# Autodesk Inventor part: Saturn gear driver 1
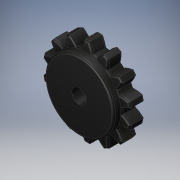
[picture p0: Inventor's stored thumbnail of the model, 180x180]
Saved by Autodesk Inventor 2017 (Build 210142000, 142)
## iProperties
Created: 2016-06
Part Number: Saturn gear driver 1
Material: Generic
Document SubType Name: Modeling
Designer: Stan
Density: 1 g/cm^3
Appearance: Glossy - Black
Author: Stan
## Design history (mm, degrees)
sketch "Sketch1" dims "d10" = 6.35
  geometry: A1 r 11.332 centre (-15.835, 1.665) between (-10.35, 11.581) and (-14.449, 12.912); A2 r 11.332 centre (-15.835, 1.665) between (-10.35, 11.581) and (-14.449, 12.912); A3 r 11.332 centre (1.9, 15.808) between (-9.373, 16.96) and (-8.988, 12.667); A4 r 11.332 centre (1.9, 15.808) between (-9.373, 16.96) and (-8.988, 12.667); A5 r 11.332 centre (-14.989, -5.37) between (-14.35, 5.944) and (-18.62, 5.364); A6 r 11.332 centre (-14.989, -5.37) between (-14.35, 5.944) and (-18.62, 5.364); A7 r 11.332 centre (-5.147, 15.067) between (-15.803, 11.213) and (-13.594, 7.513); A8 r 11.332 centre (-5.147, 15.067) between (-15.803, 11.213) and (-13.594, 7.513); A9 r 11.332 centre (-11.175, -11.342) between (-15.507, -0.871) and (-19.104, -3.246); A10 r 11.332 centre (-11.175, -11.342) between (-15.507, -0.871) and (-19.104, -3.246); A11 r 11.332 centre (-11.175, 11.342) between (-19.104, 3.246) and (-15.507, 0.871); A12 r 11.332 centre (-11.175, 11.342) between (-19.104, 3.246) and (-15.507, 0.871); A13 r 11.332 centre (-5.147, -15.067) between (-13.594, -7.513) and (-15.803, -11.213); A14 r 11.332 centre (-5.147, -15.067) between (-13.594, -7.513) and (-15.803, -11.213); A15 r 11.332 centre (-14.989, 5.37) between (-18.62, -5.364) and (-14.35, -5.944); A16 r 11.332 centre (-14.989, 5.37) between (-18.62, -5.364) and (-14.35, -5.944); A17 r 11.332 centre (1.9, -15.808) between (-8.988, -12.667) and (-9.373, -16.96); A18 r 11.332 centre (1.9, -15.808) between (-8.988, -12.667) and (-9.373, -16.96); A19 r 11.332 centre (-15.835, -1.665) between (-14.449, -12.912) and (-10.35, -11.581); A20 r 11.332 centre (-15.835, -1.665) between (-14.449, -12.912) and (-10.35, -11.581); A21 r 11.332 centre (8.571, -13.418) between (-2.602, -15.312) and (-1.086, -19.347); A22 r 11.332 centre (8.571, -13.418) between (-2.602, -15.312) and (-1.086, -19.347); A23 r 11.332 centre (-13.544, -8.371) between (-7.415, -17.902) and (-4.3, -14.925); A24 r 11.332 centre (-13.544, -8.371) between (-7.415, -17.902) and (-4.3, -14.925); A25 r 11.332 centre (13.544, -8.371) between (4.3, -14.925) and (7.415, -17.902); A26 r 11.332 centre (13.544, -8.371) between (4.3, -14.925) and (7.415, -17.902); A27 r 11.332 centre (-8.571, -13.418) between (1.086, -19.347) and (2.602, -15.312); A28 r 11.332 centre (-8.571, -13.418) between (1.086, -19.347) and (2.602, -15.312); A29 r 11.332 centre (15.835, -1.665) between (10.35, -11.581) and (14.449, -12.912); A30 r 11.332 centre (15.835, -1.665) between (10.35, -11.581) and (14.449, -12.912); A31 r 11.332 centre (-1.9, -15.808) between (9.373, -16.96) and (8.988, -12.667); A32 r 11.332 centre (-1.9, -15.808) between (9.373, -16.96) and (8.988, -12.667); A33 r 11.332 centre (14.989, 5.37) between (14.35, -5.944) and (18.62, -5.364); A34 r 11.332 centre (14.989, 5.37) between (14.35, -5.944) and (18.62, -5.364); A35 r 11.332 centre (5.147, -15.067) between (15.803, -11.213) and (13.594, -7.513); A36 r 11.332 centre (5.147, -15.067) between (15.803, -11.213) and (13.594, -7.513); A37 r 11.332 centre (11.175, 11.342) between (15.507, 0.871) and (19.104, 3.246); A38 r 11.332 centre (11.175, 11.342) between (15.507, 0.871) and (19.104, 3.246); A39 r 11.332 centre (11.175, -11.342) between (19.104, -3.246) and (15.507, -0.871); A40 r 11.332 centre (11.175, -11.342) between (19.104, -3.246) and (15.507, -0.871); A41 r 11.332 centre (5.147, 15.067) between (13.594, 7.513) and (15.803, 11.213); A42 r 11.332 centre (5.147, 15.067) between (13.594, 7.513) and (15.803, 11.213); A43 r 11.332 centre (14.989, -5.37) between (18.62, 5.364) and (14.35, 5.944); A44 r 11.332 centre (14.989, -5.37) between (18.62, 5.364) and (14.35, 5.944); A45 r 11.332 centre (-1.9, 15.808) between (8.988, 12.667) and (9.373, 16.96); A46 r 11.332 centre (-1.9, 15.808) between (8.988, 12.667) and (9.373, 16.96); A47 r 11.332 centre (15.835, 1.665) between (14.449, 12.912) and (10.35, 11.581); A48 r 11.332 centre (15.835, 1.665) between (14.449, 12.912) and (10.35, 11.581); A49 r 11.332 centre (-8.571, 13.418) between (2.602, 15.312) and (1.086, 19.347); A50 r 11.332 centre (-8.571, 13.418) between (2.602, 15.312) and (1.086, 19.347); A51 r 11.332 centre (13.544, 8.371) between (7.415, 17.902) and (4.3, 14.925); A52 r 11.332 centre (13.544, 8.371) between (7.415, 17.902) and (4.3, 14.925); A53 r 11.332 centre (1.9, 15.808) between (-9.373, 16.96) and (-8.988, 12.667); A54 r 11.332 centre (-15.835, 1.665) between (-10.35, 11.581) and (-14.449, 12.912); A55 r 11.332 centre (-5.147, 15.067) between (-15.803, 11.213) and (-13.594, 7.513); A56 r 11.332 centre (-14.989, -5.37) between (-14.35, 5.944) and (-18.62, 5.364); A57 r 11.332 centre (-11.175, 11.342) between (-19.104, 3.246) and (-15.507, 0.871); A58 r 11.332 centre (-11.175, -11.342) between (-15.507, -0.871) and (-19.104, -3.246); A59 r 11.332 centre (-14.989, 5.37) between (-18.62, -5.364) and (-14.35, -5.944); A60 r 11.332 centre (-5.147, -15.067) between (-13.594, -7.513) and (-15.803, -11.213); A61 r 11.332 centre (-15.835, -1.665) between (-14.449, -12.912) and (-10.35, -11.581); A62 r 11.332 centre (1.9, -15.808) between (-8.988, -12.667) and (-9.373, -16.96); A63 r 11.332 centre (-13.544, -8.371) between (-7.415, -17.902) and (-4.3, -14.925); A64 r 11.332 centre (8.571, -13.418) between (-2.602, -15.312) and (-1.086, -19.347)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; 1 further point
  constraints: 224 point on circle, 112 centre point, 8 horizontal alignment, 8 vertical alignment, 320 other
extrude "Extrusion1" new body sketch "Sketch1" distance "d0" = 6.35; taper "d1" = 0 deg
sketch "Sketch2"
  geometry: C1 r 15.081 at (0, 0); C2 r 3.175 at (0, 0); 1 further point
  constraints: 2 centre point, 2 coincident
  dimensions: "d2" = 30.1625 diameter of C1
extrude "Extrusion2" join sketch "Sketch2" distance "d3" = 3.175; taper "d4" = 0 deg
fillet "Fillet2" dims "d11" = 0.79375
fillet "Fillet3" dims "d12" = 0.79375
body "Solid1"
